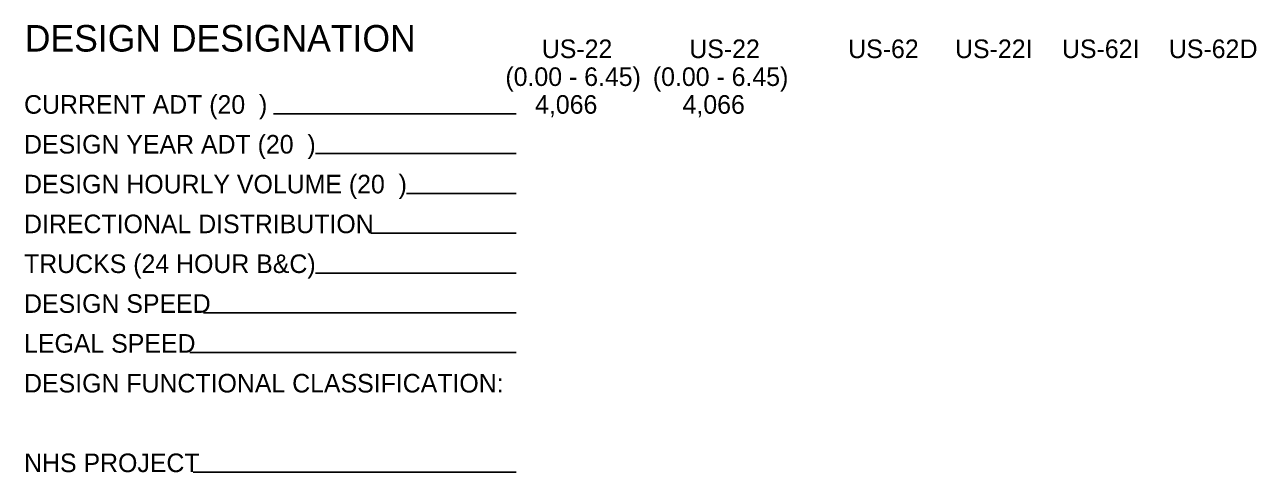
# Model space of a CAD drawing. Extents: x -12 to 164, y -741 to 24.
# Drawn here: x -11.77 to -2.5, y 5.8 to 9.17 of the extents above; entities that cross this region are included whole.
import ezdxf

# ---------------------------------------------------------------- set-up
doc = ezdxf.new("R2010")
doc.units = 0
for name, color, linetype in [('Default', 7, 'Continuous'), ('SC_Scratch1', 7, 'Continuous'), ('SH_Data', 7, 'Continuous')]:
    doc.layers.add(name, color=color, linetype=linetype)

msp = doc.modelspace()

# ---------------------------------------------------------------- linework, layer by layer
at = {"layer": 'SH_Data'}
for p, q in [((-8.0691, 8.5012), (-9.8965, 8.5012)), ((-8.0691, 8.2012), (-9.579, 8.2012)), ((-8.0691, 7.9012), (-8.8952, 7.9012)), ((-8.0691, 7.6012), (-9.1638, 7.6012)), ((-8.0691, 7.3012), (-9.579, 7.3012)), ((-8.0691, 7.0012), (-10.4216, 7.0012)), ((-8.0691, 6.7012), (-10.5254, 6.7012)), ((-8.0691, 5.8012), (-10.5006, 5.8012))]:
    msp.add_line(p, q, dxfattribs=at)

# ---------------------------------------------------------------- texts
at = {"layer": 'Default'}
for s, p in [('US-22', (-7.876, 8.9204)), ('US-22', (-6.766, 8.9204)), ('US-62', (-5.57, 8.9204)), ('US-22', (-4.7654, 8.9204)), ('I', (-4.233, 8.9204)), ('US-62', (-3.9608, 8.9204)), ('I', (-3.4284, 8.9204)), ('US-62', (-3.1562, 8.9204)), ('D', (-2.6238, 8.9204)), ('(0.00 - 6.45)', (-8.1502, 8.7104)), ('(0.00 - 6.45)', (-7.0402, 8.7104))]:
    msp.add_text(s, height=0.14, dxfattribs=at).set_placement(p)
at = {"layer": 'SC_Scratch1'}
for s, p in [('CURRENT ADT (20  )', (-11.7731, 8.5012)), ('4,066', (-7.9265, 8.5012)), ('4,066', (-6.8165, 8.5012)), ('DESIGN YEAR ADT (20  )', (-11.7731, 8.2012)), ('DESIGN HOURLY VOLUME (20  )', (-11.7731, 7.9012)), ('DIRECTIONAL DISTRIBUTION', (-11.7731, 7.6012)), ('TRUCKS (24 HOUR B&C)', (-11.7731, 7.3012)), ('DESIGN SPEED', (-11.7731, 7.0012)), ('LEGAL SPEED', (-11.7731, 6.7012)), ('DESIGN FUNCTIONAL CLASSIFICATION:', (-11.7731, 6.4012)), ('NHS PROJECT', (-11.7731, 5.8012))]:
    msp.add_text(s, height=0.14, dxfattribs=at).set_placement(p)
at = {"layer": 'SH_Data'}
msp.add_text('DESIGN DESIGNATION', height=0.2, dxfattribs=at).set_placement((-11.7675, 8.9696))

doc.saveas('drawing.dxf')
